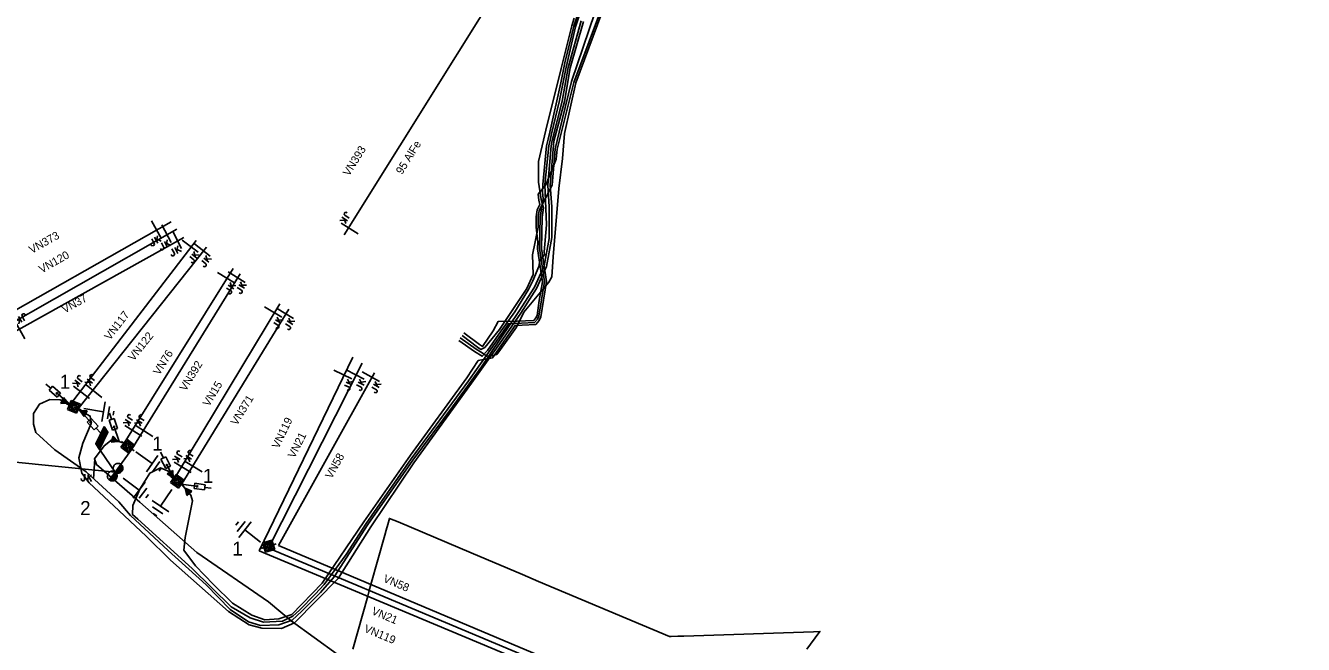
# Model space of a CAD drawing. Extents: x -540879 to -537255, y -1184046 to -1180016.
# Drawn here: x -537543.2 to -537383.5, y -1180686.9 to -1180609.6 of the extents above; entities that cross this region are included whole.
import ezdxf

# ---------------------------------------------------------------- set-up
doc = ezdxf.new("R2010")
doc.units = 0
for name, color, linetype in [('Default', 7, 'Continuous'), ('Vrstva 1', 7, 'Continuous'), ('Vrstva 11', 7, 'Continuous'), ('Vrstva 13', 7, 'Continuous'), ('Vrstva 14', 7, 'Continuous'), ('Vrstva 15', 7, 'Continuous'), ('Vrstva 16', 7, 'Continuous'), ('Vrstva 18', 7, 'Continuous'), ('Vrstva 19', 7, 'Continuous'), ('Vrstva 2', 7, 'Continuous'), ('Vrstva 3', 7, 'Continuous'), ('Vrstva 35', 7, 'Continuous'), ('Vrstva 4', 7, 'Continuous'), ('Vrstva 5', 7, 'Continuous')]:
    doc.layers.add(name, color=color, linetype=linetype)

# ---------------------------------------------------------------- blocks, each defined once
blk = doc.blocks.new('VN840')
at = {"layer": 'Vrstva 15'}
for points in [[(-0.01, 1.41), (-0.01, -1.09)], [(-1.51, -1.24), (-1.51, -1.15)], [(-1.48, -1.35), (-1.51, -1.24)], [(-1.33, -1.42), (-1.48, -1.35)], [(-1.27, -1.42), (-1.33, -1.42)], [(-1.13, -1.35), (-1.27, -1.42)], [(-1.09, -1.24), (-1.13, -1.35)], [(-1.09, -0.59), (-1.09, -1.24)], [(-0.68, -0.59), (-0.68, -1.42)], [(-0.68, -1.11), (-0.27, -0.59)], [(-0.54, -0.94), (-0.2, -1.42)]]:
    blk.add_lwpolyline(points, dxfattribs=at)
blk = doc.blocks.new('VN890')
at = {"layer": 'Vrstva 4'}
for points in [[(-0.41, 0.41), (0.41, 0)], [(-0.41, -0.41), (-0.41, 0.41)], [(0.41, 0), (-0.41, -0.41)], [(-0.34, 0.31), (0.27, 0), (-0.34, -0.3), (-0.34, 0.31)], [(-0.26, 0.2), (0.1, 0), (-0.26, -0.18), (-0.26, 0.2)], [(-0.19, 0.09), (-0.04, 0), (-0.19, -0.08), (-0.19, 0.09)], [(-0.16, -0.01), (-0.16, 0.03), (-0.13, 0.01), (-0.16, -0.01)]]:
    blk.add_lwpolyline(points, dxfattribs=at)
blk = doc.blocks.new('VN820')
at = {"layer": 'Vrstva 13'}
for points in [[(0, 0), (0, -2.1)], [(-0.32, -1.63), (0.34, -1.63)], [(-0.32, -2.95), (-0.32, -1.63)], [(0.34, -2.95), (-0.32, -2.95)], [(0, -2.1), (-0.12, -1.86)], [(0, -2.1), (0.12, -1.86)], [(0, -2.95), (0, -3.75)], [(0.34, -1.63), (0.34, -2.95)]]:
    blk.add_lwpolyline(points, dxfattribs=at)
blk = doc.blocks.new('VN810')
at = {"layer": 'Vrstva 14'}
for points in [[(0, -1.25), (0, -3.75)], [(1.25, -3.75), (-1.25, -3.75)], [(0.77, -4.37), (-0.8, -4.37)], [(0, -5), (-0.25, -5)], [(0.27, -5), (0, -5)]]:
    blk.add_lwpolyline(points, dxfattribs=at)
blk = doc.blocks.new('VN450')
at = {"layer": 'Vrstva 2'}
for points in [[(0, 0), (-0.01, 0.13), (-0.03, 0.25), (-0.06, 0.38), (-0.11, 0.5), (-0.16, 0.61), (-0.23, 0.72), (-0.31, 0.82), (-0.4, 0.91), (-0.5, 0.99), (-0.61, 1.06), (-0.72, 1.11), (-0.84, 1.16), (-0.97, 1.19), (-1.09, 1.21), (-1.22, 1.22), (-1.35, 1.21), (-1.47, 1.19), (-1.59, 1.16), (-1.71, 1.11), (-1.83, 1.06), (-1.93, 0.99), (-2.03, 0.91), (-2.12, 0.82), (-2.2, 0.72), (-2.27, 0.61), (-2.33, 0.5), (-2.38, 0.38), (-2.41, 0.25), (-2.43, 0.13), (-2.44, 0), (-2.43, -0.13), (-2.41, -0.25), (-2.38, -0.38), (-2.33, -0.5), (-2.27, -0.61), (-2.2, -0.72), (-2.12, -0.82), (-2.03, -0.91), (-1.93, -0.99), (-1.83, -1.06), (-1.71, -1.11), (-1.59, -1.16), (-1.47, -1.19), (-1.35, -1.21), (-1.22, -1.22), (-1.09, -1.21), (-0.97, -1.19), (-0.84, -1.16), (-0.72, -1.11), (-0.61, -1.06), (-0.5, -0.99), (-0.4, -0.91), (-0.31, -0.82), (-0.23, -0.72), (-0.16, -0.61), (-0.11, -0.5), (-0.06, -0.38), (-0.03, -0.25), (-0.01, -0.13), (0, 0)], [(-2.44, 0), (2.44, 0)], [(2.44, 0), (2.43, 0.13), (2.41, 0.25), (2.38, 0.38), (2.33, 0.5), (2.27, 0.61), (2.2, 0.72), (2.12, 0.82), (2.03, 0.91), (1.94, 0.99), (1.83, 1.06), (1.71, 1.11), (1.6, 1.16), (1.47, 1.19), (1.35, 1.21), (1.22, 1.22), (1.09, 1.21), (0.97, 1.19), (0.84, 1.16), (0.72, 1.11), (0.61, 1.06), (0.5, 0.99), (0.4, 0.91), (0.31, 0.82), (0.23, 0.72), (0.16, 0.61), (0.11, 0.5), (0.06, 0.38), (0.03, 0.25), (0.01, 0.13), (0, 0), (0.01, -0.13), (0.03, -0.25), (0.06, -0.38), (0.11, -0.5), (0.16, -0.61), (0.23, -0.72), (0.31, -0.82), (0.4, -0.91), (0.5, -0.99), (0.61, -1.06), (0.72, -1.11), (0.84, -1.16), (0.97, -1.19), (1.09, -1.21), (1.22, -1.22), (1.35, -1.21), (1.47, -1.19), (1.6, -1.16), (1.71, -1.11), (1.83, -1.06), (1.94, -0.99), (2.03, -0.91), (2.12, -0.82), (2.2, -0.72), (2.27, -0.61), (2.33, -0.5), (2.38, -0.38), (2.41, -0.25), (2.43, -0.13), (2.44, 0)], [(-2.4, -0.31), (-0.04, -0.31)], [(-2.26, -0.61), (-0.17, -0.61)], [(-2.01, -0.92), (-0.42, -0.92)], [(0.04, -0.31), (2.4, -0.31)], [(0.17, -0.61), (2.27, -0.61)], [(0.42, -0.92), (2.02, -0.92)]]:
    blk.add_lwpolyline(points, dxfattribs=at)
blk = doc.blocks.new('VN001')
at = {"layer": 'Default'}
for p, q in [((1.85, 3.23), (4.26, 3.23)), ((1.87, 3.28), (4.29, 3.28)), ((1.9, 3.33), (4.32, 3.33)), ((1.93, 3.38), (4.35, 3.38)), ((1.96, 3.43), (4.37, 3.43)), ((1.99, 3.48), (4.4, 3.48)), ((2.02, 3.53), (4.43, 3.53)), ((2.05, 3.58), (4.46, 3.58)), ((2.07, 3.63), (4.49, 3.63)), ((2.1, 3.68), (4.52, 3.68)), ((2.13, 3.73), (2.54, 3.73)), ((1.73, 3.03), (4.14, 3.03)), ((1.76, 3.08), (4.17, 3.08)), ((1.79, 3.13), (4.2, 3.13)), ((1.82, 3.18), (4.23, 3.18))]:
    blk.add_line(p, q, dxfattribs=at)
blk.add_lwpolyline([(2.13, 3.73), (0, 0)], dxfattribs=at)
blk.add_lwpolyline([(4.55, 3.73), (2.13, 3.73), (1.7, 2.98), (4.12, 2.99)], close=True, dxfattribs=at)
blk = doc.blocks.new('VN470')
at = {"layer": 'Vrstva 2'}
for points in [[(-1.23, 1.22), (1.23, 1.22)], [(-1.23, -1.23), (-1.23, 1.22)], [(-0.92, 0.9), (0.92, 0.9)], [(-0.92, -0.95), (-0.92, 0.9)], [(-0.61, 0.61), (0.61, 0.61)], [(-0.61, -0.62), (-0.61, 0.61)], [(-0.31, -0.27), (-0.31, 0.34)], [(-0.31, 0.34), (0.31, 0.34)], [(0, 1.22), (0, 1.97)], [(0.31, 0.34), (0.31, -0.27)], [(0.61, 0.61), (0.61, -0.62)], [(0.92, 0.9), (0.92, -0.95)], [(1.23, 1.22), (1.23, -1.23)], [(1.23, -1.23), (-1.23, -1.23)], [(0.92, -0.95), (-0.92, -0.95)], [(0.61, -0.62), (-0.61, -0.62)], [(0.31, -0.27), (-0.31, -0.27)], [(0, -1.23), (0, -1.98)]]:
    blk.add_lwpolyline(points, dxfattribs=at)

msp = doc.modelspace()

# ---------------------------------------------------------------- linework, layer by layer
at = {"layer": 'Vrstva 1'}
for points in [[(-537442.07, -1180443.04), (-537428.24, -1180472.48), (-537455.15, -1180540.11), (-537475.32, -1180590.93), (-537503.35, -1180635.79)], [(-537549.42, -1180647.98), (-537524.99, -1180634.15)], [(-537548.92, -1180649.04), (-537524.29, -1180635.07)], [(-537548.49, -1180650.05), (-537523.4, -1180636.11)], [(-537537.55, -1180656.91), (-537521.87, -1180636.49)], [(-537536.66, -1180657.56), (-537520.59, -1180637.31)], [(-537516.36, -1180640.64), (-537529.9, -1180662.53), (-537531.99, -1180665.4)], [(-537517.24, -1180639.98), (-537530.88, -1180661.78)], [(-537524.62, -1180666.27), (-537524.21, -1180665.58), (-537511.41, -1180644.38)], [(-537523.69, -1180666.91), (-537523.33, -1180666.34), (-537510.28, -1180645.07)], [(-537513.97, -1180675.24), (-537502.29, -1180651.05)], [(-537512.82, -1180674.92), (-537501.1, -1180651.8)], [(-537511.59, -1180674.55), (-537499.56, -1180652.99)], [(-537531.99, -1180665.41), (-537572.36, -1180661.38), (-537627.26, -1180751.9)], [(-537513.97, -1180675.24), (-537464.53, -1180695.92), (-537378.21, -1180693.51), (-537311.07, -1180690.92), (-537289.98, -1180689.81)], [(-537512.82, -1180674.92), (-537464.4, -1180695.21), (-537378.15, -1180692.5), (-537311.07, -1180689.98), (-537289.7, -1180688.86)], [(-537511.59, -1180674.55), (-537464.27, -1180694.51), (-537378.16, -1180691.54), (-537311.24, -1180689.01), (-537289.41, -1180687.88)]]:
    msp.add_lwpolyline(points, dxfattribs=at)
at = {"layer": 'Vrstva 35'}
msp.add_lwpolyline([(-537502.27, -1180687.5), (-537500.42, -1180680.91), (-537500.22, -1180680.2), (-537500.01, -1180679.43), (-537498.29, -1180673.29), (-537498.11, -1180672.66), (-537497.91, -1180671.95), (-537497.7, -1180671.18), (-537496.63, -1180671.63), (-537487.5, -1180675.48), (-537481.08, -1180678.19), (-537479.05, -1180679.05), (-537462.69, -1180685.95), (-537462.5, -1180685.94), (-537461.67, -1180685.91), (-537460.89, -1180685.89), (-537444.71, -1180685.33), (-537443.9, -1180685.3), (-537444.48, -1180686.08), (-537445.07, -1180686.87), (-537445.54, -1180687.5)], dxfattribs=at)
at = {"layer": 'Vrstva 5'}
for points in [[(-537524.62, -1180666.27), (-537525.17, -1180665.35), (-537526.3, -1180664.85), (-537527.67, -1180665.53), (-537528.9, -1180667.53), (-537529.77, -1180669.56), (-537529.8, -1180670.7), (-537529.16, -1180671.26), (-537522.37, -1180677.44), (-537517.48, -1180682.21), (-537515.12, -1180683.61), (-537513.44, -1180684.15), (-537511.08, -1180684), (-537509.77, -1180683.38), (-537508.93, -1180682.63), (-537507, -1180680.65), (-537505.88, -1180679.44), (-537503.12, -1180675.71), (-537500.63, -1180671.83), (-537494.99, -1180663.76), (-537487.81, -1180654.01), (-537483.52, -1180647.91), (-537482.83, -1180646.87), (-537479.55, -1180646.72), (-537479.2, -1180646.29), (-537479.01, -1180645.91), (-537478.3, -1180641.62), (-537478.93, -1180637.48), (-537478.87, -1180633.55), (-537478.49, -1180631.23), (-537478.59, -1180630.46), (-537478.54, -1180629.47), (-537478.05, -1180624.67), (-537477.86, -1180623.84), (-537477.65, -1180622.95), (-537476.26, -1180616.8), (-537475.73, -1180614.08), (-537475.23, -1180612.11), (-537474.67, -1180609.73), (-537472.18, -1180602.23)], [(-537489.03, -1180648.97), (-537487.09, -1180650.34), (-537486.1, -1180650.93), (-537485.46, -1180650.21), (-537483.73, -1180647.77), (-537482.04, -1180645.39), (-537480.32, -1180642.6), (-537479.76, -1180641.51), (-537479.01, -1180639.71), (-537478.9, -1180638.98), (-537478.31, -1180638.27), (-537478.37, -1180637.88), (-537478.09, -1180634.53), (-537478.29, -1180629.48), (-537477.79, -1180624.65), (-537477.62, -1180623.93), (-537477.44, -1180623.15), (-537476.44, -1180618.98), (-537475.63, -1180614.85), (-537474.43, -1180609.8), (-537471.83, -1180601.99)], [(-537470.61, -1180606.58), (-537474.4, -1180616.8), (-537475.82, -1180623.1), (-537476.09, -1180626.22), (-537476.52, -1180629.99), (-537477.24, -1180638.54), (-537477.4, -1180641.02), (-537477.76, -1180641.69), (-537480.92, -1180645.42), (-537481.83, -1180647.3), (-537483.83, -1180650.09), (-537484.28, -1180650.72), (-537485, -1180650.87), (-537485.53, -1180650.93), (-537486.1, -1180650.52), (-537486.88, -1180650.05), (-537488.87, -1180648.62)], [(-537470.84, -1180606.49), (-537474.64, -1180616.73), (-537476.75, -1180625.06), (-537476.86, -1180626.33), (-537478.14, -1180629.53), (-537479.13, -1180630.7), (-537479.04, -1180631.43), (-537478.89, -1180632), (-537479.24, -1180632.67), (-537479.37, -1180633.51), (-537479.38, -1180634.81), (-537479.17, -1180636.65), (-537479.18, -1180637.5), (-537478.55, -1180641.63), (-537478.98, -1180643.98), (-537479.24, -1180645.83), (-537479.41, -1180646.15), (-537479.67, -1180646.47), (-537481.75, -1180646.57), (-537484.12, -1180646.6), (-537484.75, -1180647.76), (-537486.07, -1180649.7), (-537486.45, -1180649.46), (-537488.4, -1180648)], [(-537523.69, -1180666.91), (-537522.52, -1180668.27), (-537522.34, -1180668.99), (-537523.25, -1180673.56), (-537523.4, -1180675.14), (-537521.95, -1180677.1), (-537519.71, -1180679.45), (-537517.3, -1180681.78), (-537514.9, -1180683.27), (-537513.27, -1180683.85), (-537511.51, -1180683.74), (-537509.9, -1180683.17), (-537506.1, -1180679.26), (-537500.91, -1180671.62), (-537495.09, -1180663.27), (-537488.04, -1180653.62), (-537486.6, -1180651.47), (-537484.82, -1180651.13), (-537482, -1180647.09), (-537481.11, -1180647.04), (-537479.42, -1180646.96), (-537478.98, -1180646.45), (-537478.77, -1180646), (-537478.05, -1180641.61), (-537478.68, -1180637.46), (-537478.62, -1180633.57), (-537478.44, -1180632.41), (-537478.75, -1180631.37), (-537479.06, -1180629.18), (-537479.06, -1180626.6), (-537478.17, -1180622.72), (-537476.25, -1180615), (-537474.91, -1180609.66), (-537474.63, -1180608.7)], [(-537488.61, -1180648.36), (-537486.7, -1180649.8), (-537486.26, -1180650.09), (-537485.76, -1180649.83), (-537483.93, -1180647.61), (-537480.54, -1180642.48), (-537479.74, -1180640.72), (-537479.8, -1180638.27), (-537479.13, -1180634.83), (-537479.12, -1180633.53), (-537479, -1180632.75), (-537477.37, -1180629.59), (-537477, -1180625.02), (-537476.49, -1180622.96), (-537474.96, -1180616.62), (-537472.04, -1180608.06)], [(-537537.55, -1180656.91), (-537538.87, -1180656.37), (-537540.17, -1180656.34), (-537541.44, -1180656.9), (-537542.2, -1180658.07), (-537542.19, -1180659.42), (-537541.9, -1180660.46), (-537539.51, -1180662.63), (-537535.62, -1180665.35), (-537531.54, -1180669.11), (-537530.05, -1180670.81), (-537525.36, -1180675.2), (-537520.63, -1180679.49), (-537517.6, -1180682.56), (-537515.32, -1180684.08), (-537513.8, -1180684.57), (-537511.54, -1180684.46), (-537509.88, -1180683.89), (-537508.67, -1180682.78), (-537506.32, -1180680.44), (-537504.6, -1180678.49), (-537500.39, -1180671.96), (-537494.79, -1180663.9), (-537489.83, -1180657.24), (-537486.19, -1180652.27), (-537481.52, -1180645.33), (-537479.58, -1180642.32), (-537478.36, -1180639.64), (-537477.74, -1180636.24), (-537477.72, -1180632.29), (-537477.92, -1180629.59), (-537477.48, -1180624.64), (-537477.38, -1180623.98), (-537476.13, -1180619.06), (-537475.36, -1180614.86), (-537473.73, -1180609.06)], [(-537536.66, -1180657.56), (-537535.11, -1180658.4), (-537534.98, -1180659.35), (-537536.04, -1180661.78), (-537536.52, -1180663.62), (-537536.16, -1180665.52), (-537535.22, -1180666.75), (-537532.16, -1180669.61), (-537528.12, -1180673.42), (-537525.07, -1180676.39), (-537517.8, -1180682.79), (-537515.23, -1180684.49), (-537513.67, -1180684.9), (-537511.21, -1180684.94), (-537509.55, -1180684.22), (-537504.1, -1180678.7), (-537500.04, -1180672.25), (-537494.67, -1180664.23), (-537487.43, -1180654.31), (-537483.89, -1180649.35), (-537481.28, -1180645.57), (-537479.32, -1180642.47), (-537478.07, -1180639.73), (-537477.39, -1180636.09), (-537477.42, -1180632.28), (-537477.62, -1180629.59), (-537477.17, -1180624.08), (-537475.84, -1180619.13), (-537475.11, -1180614.92), (-537473.44, -1180609.14)], [(-537530.88, -1180661.78), (-537532.37, -1180661.32), (-537533.38, -1180662.14), (-537534.59, -1180663.75), (-537534.3, -1180664.46), (-537528.92, -1180669.15), (-537521.77, -1180675.43), (-537512.81, -1180681.59), (-537510, -1180683.99), (-537501.37, -1180690.23)]]:
    msp.add_lwpolyline(points, dxfattribs=at)

# ---------------------------------------------------------------- block references
at = {"layer": 'Vrstva 11', "rotation": 64.19884263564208}
msp.add_blockref('VN001', (-537531.99, -1180665.41), dxfattribs=at)
at = {"layer": 'Vrstva 13'}
for name, p, xscale, yscale, rotation in [('VN470', (-537537.14, -1180657.26), 0.5, 0.5, 67.58060832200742), ('VN470', (-537530.41, -1180662.16), 0.5, 0.5, 54.32645550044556), ('VN450', (-537531.99, -1180665.41), 0.5, 0.5, 53.00006765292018), ('VN470', (-537524.21, -1180666.56), 0.5000000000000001, 0.4999999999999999, 54.302605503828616), ('VN470', (-537512.8, -1180674.65), 0.5000000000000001, 0.4999999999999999, 106.41475274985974)]:
    msp.add_blockref(name, p, dxfattribs=dict(at, xscale=xscale, yscale=yscale, rotation=rotation))
at = {"layer": 'Vrstva 15'}
for p, rotation in [((-537537.14, -1180657.26), 80.76815297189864), ((-537530.41, -1180662.16), 54.372091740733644), ((-537531.99, -1180665.4), 53.09526546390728), ((-537524.21, -1180666.56), -34.214344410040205), ((-537512.82, -1180674.92), -128.29809441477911)]:
    msp.add_blockref('VN810', p, dxfattribs=dict(at, rotation=rotation))
at = {"layer": 'Vrstva 16'}
for p, rotation in [((-537537.77, -1180656.82), -129.9011713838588), ((-537536.36, -1180657.73), 42.580173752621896), ((-537531.5, -1180661.6), -161.7373701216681), ((-537524.62, -1180666.27), -153.03157621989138), ((-537523.69, -1180666.91), 82.16965594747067)]:
    msp.add_blockref('VN820', p, dxfattribs=dict(at, rotation=rotation))
at = {"layer": 'Vrstva 18'}
for p, rotation in [((-537526.76, -1180635.23), 29.3704610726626), ((-537502.8, -1180634.91), -121.99631107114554), ((-537525.5, -1180635.76), 27.55182790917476), ((-537524.18, -1180636.51), 27.00831947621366), ((-537522.47, -1180637.27), 52.47536953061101), ((-537520.95, -1180637.77), 51.641455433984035), ((-537517.99, -1180641.19), 58.383730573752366), ((-537516.66, -1180641.12), 57.93011386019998), ((-537512.09, -1180645.5), 58.883847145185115), ((-537510.63, -1180645.64), 58.46351669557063), ((-537543.97, -1180647.54), -150.94920141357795), ((-537536.32, -1180655.34), -127.52463055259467), ((-537534.78, -1180655.2), -128.35854451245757), ((-537503.37, -1180653.29), 64.36561944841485), ((-537501.84, -1180653.28), 63.10967775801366), ((-537499.87, -1180653.55), 60.58048607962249), ((-537529.87, -1180660.17), -121.61626936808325), ((-537528.46, -1180660.2), -122.06988613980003), ((-537523.69, -1180664.72), -121.11598892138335), ((-537522.3, -1180664.66), -121.53513895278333), ((-537534.63, -1180665.16), -3.8780361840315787)]:
    msp.add_blockref('VN840', p, dxfattribs=dict(at, rotation=rotation))
at = {"layer": 'Vrstva 19'}
for p, rotation in [((-537538.23, -1180656.63), -22.41939157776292), ((-537536.04, -1180657.9), 151.6618332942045), ((-537531.98, -1180661.43), -20.006861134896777), ((-537524.93, -1180665.75), -59.17381941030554), ((-537522.98, -1180667.73), 130.70915002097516)]:
    msp.add_blockref('VN890', p, dxfattribs=dict(at, rotation=rotation))

# ---------------------------------------------------------------- texts
at = {"layer": 'Vrstva 14'}
for s, p in [('1', (-537538.91, -1180654.99)), ('1', (-537527.34, -1180662.71)), ('1', (-537521.03, -1180666.75)), ('2', (-537536.36, -1180670.77)), ('1', (-537517.34, -1180675.83))]:
    msp.add_text(s, height=1.75, dxfattribs=at).set_placement(p)
at = {"layer": 'Vrstva 2'}
msp.add_text('95 AlFe', height=1, rotation=58.004, dxfattribs=at).set_placement((-537496.13, -1180628.31))
at = {"layer": 'Vrstva 3'}
for s, rotation, p in [('VN393', 58.004, (-537502.75, -1180628.53)), ('VN373', 29.51, (-537542.41, -1180638.16)), ('VN120', 29.563, (-537541.17, -1180640.6)), ('VN37', 29.051, (-537538.3, -1180645.61)), ('VN117', 52.475, (-537532.63, -1180649.01)), ('VN122', 51.571, (-537529.68, -1180651.61)), ('VN76', 57.971, (-537526.47, -1180653.38)), ('VN392', 58.268, (-537523.17, -1180655.38)), ('VN15', 58.884, (-537520.26, -1180657.3)), ('VN371', 58.464, (-537516.77, -1180659.66)), ('VN119', 64.228, (-537511.56, -1180662.56)), ('VN21', 63.11, (-537509.56, -1180663.75)), ('VN58', 60.837, (-537504.93, -1180666.32)), ('VN58', 337.13, (-537498.57, -1180679.07)), ('VN21', 337.258, (-537500.02, -1180683.12)), ('VN119', 337.307, (-537500.96, -1180685.32))]:
    msp.add_text(s, height=1, rotation=rotation, dxfattribs=at).set_placement(p)

doc.saveas('drawing.dxf')
